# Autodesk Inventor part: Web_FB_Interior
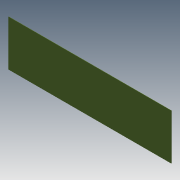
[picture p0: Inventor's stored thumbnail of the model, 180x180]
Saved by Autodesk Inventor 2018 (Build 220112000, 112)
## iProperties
Created: 2018-02
Part Number: Web_FB_Interior
Material: Steel, Mild
Document SubType Name: Modeling
Designer: STK
Mass: 821574 g
Surface Area: 216400 cm^2
Volume: 104659 cm^3
Density: 7.85 g/cm^3
Appearance: Olive Green
Author: STK
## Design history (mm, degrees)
derived "Web_FB_end.ipt"
feature "Solid1::Web_FB_end.ipt" dims "ScaleForDerivedMember" = 10
tag "TaggingFeature1"
body "Solid1"
other parameters: "Height" = 1371.6, "Total_Length" = 4876.8, "Thickness" = 10.0584, "d3" = 0
